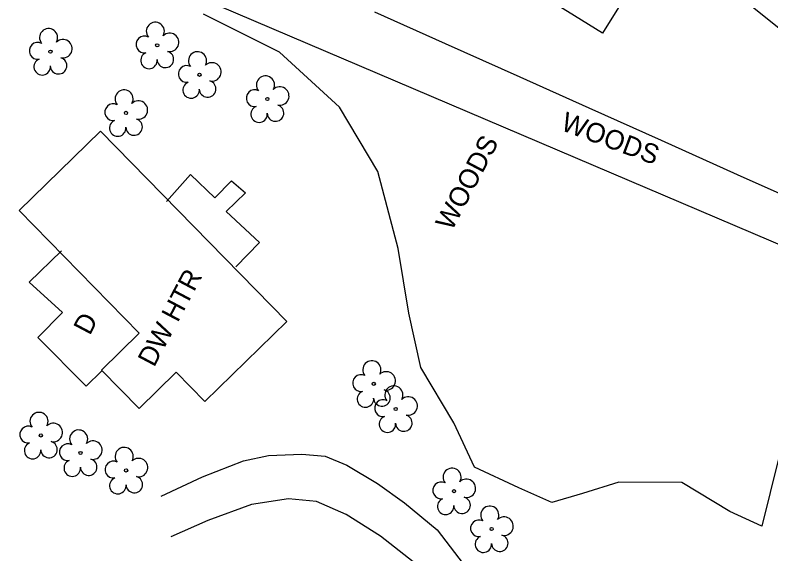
# Model space of a CAD drawing. Extents: x 1149843 to 1151668, y 621784 to 624721.
# Drawn here: x 1150484.2 to 1150639.4, y 623160.4 to 623271.1 of the extents above; entities that cross this region are included whole.
import ezdxf

# ---------------------------------------------------------------- set-up
doc = ezdxf.new("R2010")
doc.units = 0
for name, color, linetype in [('Exist Building', 7, 'Continuous'), ('Exist Building Text', 7, 'Continuous'), ('Exist Other Culture Area Outline', 7, 'Continuous'), ('Exist Other Culture Area Outline Text', 7, 'Continuous'), ('Exist Property Line', 7, 'Continuous'), ('Exist Roads Soil', 7, 'Continuous'), ('Exist Utilities Power UG Cable SUE', 7, 'Continuous'), ('Exist Vegetation Tree CELL', 7, 'Continuous'), ('Exist Vegetation Woods Line', 7, 'Continuous'), ('Exist Vegetation Woods Line Text', 7, 'Continuous')]:
    doc.layers.add(name, color=color, linetype=linetype)

msp = doc.modelspace()

# ---------------------------------------------------------------- linework, layer by layer
at = {"layer": 'Exist Building'}
for points in [[(1150604.77, 623267.36), (1150590.97, 623275.97), (1150597.72, 623286.8), (1150611.53, 623278.19)], [(1150501.76, 623247.25), (1150540, 623208.17), (1150523.17, 623191.7), (1150517.25, 623197.75), (1150509.65, 623190.31), (1150501.95, 623198.18), (1150509.69, 623205.74), (1150485.06, 623230.91)]]:
    msp.add_lwpolyline(points, close=True, dxfattribs=at)
at = {"layer": 'Exist Other Culture Area Outline'}
for points in [[(1150515.27, 623232.81), (1150520.21, 623238.32), (1150525.25, 623233.57), (1150528.63, 623237.01), (1150531.53, 623234.57), (1150527.52, 623230.72), (1150534.38, 623224.4), (1150529.54, 623219.36)], [(1150493.74, 623222.68), (1150487.07, 623216.23), (1150493.96, 623209.96), (1150488.91, 623204.88), (1150498.8, 623194.86), (1150502.02, 623197.99)]]:
    msp.add_lwpolyline(points, dxfattribs=at)
at = {"layer": 'Exist Property Line'}
msp.add_line((1150220.73, 623403.16), (1150704.95, 623196.74), dxfattribs=at)
at = {"layer": 'Exist Roads Soil'}
for points in [[(1150514.2, 623172.26), (1150522.71, 623176.23), (1150531.12, 623179.54), (1150536.24, 623180.65), (1150543.08, 623180.92), (1150547.86, 623180.49), (1150552.32, 623178.64), (1150558.64, 623174.89), (1150564.18, 623170.9), (1150570.87, 623165.34), (1150577.1, 623157.23), (1150585.07, 623144.02), (1150593.33, 623126.07), (1150599.51, 623111.6), (1150603.78, 623098.72), (1150608, 623086.29), (1150611.91, 623071.88), (1150616.83, 623060.13), (1150620.21, 623054.9)], [(1150606.55, 623064.28), (1150602.64, 623077.14), (1150596.78, 623095.46), (1150592.23, 623109.09), (1150586.2, 623126.59), (1150577.23, 623145.28), (1150572.12, 623152.47), (1150566.89, 623158.02), (1150559.2, 623164.09), (1150552.15, 623168.48), (1150546.12, 623171.19), (1150540.33, 623171.73), (1150532.77, 623170.53), (1150523.75, 623167.29), (1150516.15, 623163.9)]]:
    msp.add_lwpolyline(points, dxfattribs=at)
at = {"layer": 'Exist Utilities Power UG Cable SUE'}
msp.add_lwpolyline([(1150633.5, 623274.51), (1150655.87, 623256.56), (1150671.72, 623238.23), (1150681.72, 623223.65), (1150687.35, 623201.98)], dxfattribs=at)
at = {"layer": 'Exist Vegetation Tree CELL'}
for p, q in [((1150513.39, 623264.87), (1150513.39, 623264.87)), ((1150491.47, 623263.57), (1150491.47, 623263.57)), ((1150522.06, 623258.81), (1150522.06, 623258.81)), ((1150536.01, 623253.85), (1150536.01, 623253.85)), ((1150506.98, 623250.98), (1150506.98, 623250.98)), ((1150557.84, 623195.35), (1150557.84, 623195.35)), ((1150562.35, 623190.19), (1150562.35, 623190.19)), ((1150489.5, 623184.75), (1150489.5, 623184.75)), ((1150497.64, 623181.14), (1150497.64, 623181.14)), ((1150507, 623177.56), (1150507, 623177.56)), ((1150574.3, 623173.3), (1150574.3, 623173.3)), ((1150582.04, 623165.52), (1150582.04, 623165.52))]:
    msp.add_line(p, q, dxfattribs=at)
for centre in [(1150513.39, 623264.87), (1150491.47, 623263.57), (1150522.06, 623258.81), (1150536.01, 623253.85), (1150506.98, 623250.98), (1150557.84, 623195.35), (1150562.35, 623190.19), (1150489.5, 623184.75), (1150497.64, 623181.14), (1150507, 623177.56), (1150574.3, 623173.3), (1150582.04, 623165.52)]:
    msp.add_circle(centre, 0.326, dxfattribs=at)
for centre, radius, start, end in [((1150513, 623267.74), 1.86, 330.1651, 219.7134), ((1150491.09, 623266.44), 1.86, 330.1651, 219.7134), ((1150515.94, 623265.46), 1.9, 257.1011, 134.1999), ((1150494.02, 623264.16), 1.9, 257.1011, 134.1999), ((1150510.78, 623265.02), 1.73, 62.6636, 279.3457), ((1150488.86, 623263.72), 1.73, 62.6636, 279.3457), ((1150511.69, 623261.75), 1.69, 111.5671, 6.231), ((1150515.06, 623261.97), 1.7, 181.2822, 74.56), ((1150521.67, 623261.69), 1.86, 330.1651, 219.7134), ((1150489.77, 623260.45), 1.69, 111.5671, 6.231), ((1150493.14, 623260.67), 1.7, 181.2822, 74.56), ((1150524.61, 623259.4), 1.9, 257.1011, 134.1999), ((1150519.45, 623258.97), 1.73, 62.6636, 279.3457), ((1150535.62, 623256.72), 1.86, 330.1651, 219.7134), ((1150520.35, 623255.69), 1.69, 111.5671, 6.231), ((1150523.73, 623255.91), 1.7, 181.2822, 74.56), ((1150506.59, 623253.85), 1.86, 330.1651, 219.7134), ((1150533.4, 623254), 1.73, 62.6636, 279.3457), ((1150538.55, 623254.44), 1.9, 257.1011, 134.1999), ((1150509.53, 623251.57), 1.9, 257.1011, 134.1999), ((1150504.37, 623251.13), 1.73, 62.6636, 279.3457), ((1150534.3, 623250.73), 1.69, 111.5671, 6.231), ((1150537.68, 623250.95), 1.7, 181.2822, 74.56), ((1150505.27, 623247.86), 1.69, 111.5671, 6.231), ((1150508.65, 623248.08), 1.7, 181.2822, 74.56), ((1150557.46, 623198.23), 1.86, 330.1651, 219.7134), ((1150560.39, 623195.94), 1.9, 257.1011, 134.1999), ((1150555.24, 623195.51), 1.73, 62.6636, 279.3457), ((1150561.97, 623193.07), 1.86, 330.1651, 219.7134), ((1150556.14, 623192.23), 1.69, 111.5671, 6.231), ((1150559.52, 623192.45), 1.7, 181.2822, 74.56), ((1150559.74, 623190.35), 1.73, 62.6636, 279.3457), ((1150564.9, 623190.78), 1.9, 257.1011, 134.1999), ((1150489.12, 623187.63), 1.86, 330.1651, 219.7134), ((1150560.65, 623187.07), 1.69, 111.5671, 6.231), ((1150564.02, 623187.29), 1.7, 181.2822, 74.56), ((1150486.9, 623184.91), 1.73, 62.6636, 279.3457), ((1150492.05, 623185.34), 1.9, 257.1011, 134.1999), ((1150497.26, 623184.01), 1.86, 330.1651, 219.7134), ((1150500.19, 623181.73), 1.9, 257.1011, 134.1999), ((1150487.8, 623181.63), 1.69, 111.5671, 6.231), ((1150491.17, 623181.85), 1.7, 181.2822, 74.56), ((1150495.04, 623181.29), 1.73, 62.6636, 279.3457), ((1150506.62, 623180.44), 1.86, 330.1651, 219.7134), ((1150495.94, 623178.02), 1.69, 111.5671, 6.231), ((1150499.32, 623178.24), 1.7, 181.2822, 74.56), ((1150504.4, 623177.72), 1.73, 62.6636, 279.3457), ((1150509.55, 623178.15), 1.9, 257.1011, 134.1999), ((1150573.92, 623176.17), 1.86, 330.1651, 219.7134), ((1150505.3, 623174.44), 1.69, 111.5671, 6.231), ((1150508.68, 623174.67), 1.7, 181.2822, 74.56), ((1150576.85, 623173.89), 1.9, 257.1011, 134.1999), ((1150571.7, 623173.45), 1.73, 62.6636, 279.3457), ((1150572.6, 623170.18), 1.69, 111.5671, 6.231), ((1150575.97, 623170.4), 1.7, 181.2822, 74.56), ((1150581.66, 623168.39), 1.86, 330.1651, 219.7134), ((1150584.59, 623166.11), 1.9, 257.1011, 134.1999), ((1150579.44, 623165.67), 1.73, 62.6636, 279.3457), ((1150580.34, 623162.4), 1.69, 111.5671, 6.231), ((1150583.71, 623162.62), 1.7, 181.2822, 74.56)]:
    msp.add_arc(centre, radius, start, end, dxfattribs=at)
at = {"layer": 'Exist Vegetation Woods Line'}
for points in [[(1150644.39, 623194.07), (1150637.54, 623166.13), (1150630.92, 623169.12), (1150621.1, 623175.08), (1150608.18, 623175.12), (1150600.66, 623172.79), (1150594.42, 623170.97), (1150587.61, 623173.97), (1150578.51, 623178.25), (1150574.31, 623187.33), (1150567.53, 623198.68), (1150565.04, 623209.88), (1150562.87, 623223.16), (1150558.68, 623238.96), (1150550.83, 623252.19), (1150538.48, 623263.47), (1150522.9, 623271.24)], [(1150558, 623271.74), (1150572.48, 623265.25), (1150587.82, 623258.37), (1150602.02, 623252), (1150616.84, 623245.36), (1150632.46, 623238.36), (1150647.96, 623231.41)]]:
    msp.add_lwpolyline(points, dxfattribs=at)

# ---------------------------------------------------------------- texts
at = {"layer": 'Exist Building Text'}
msp.add_text('DW HTR', height=4, rotation=62.15, dxfattribs=at).set_placement((1150512.74, 623198.6))
at = {"layer": 'Exist Other Culture Area Outline Text'}
msp.add_text('D', height=4, rotation=62.15, dxfattribs=at).set_placement((1150499.54, 623205.13))
at = {"layer": 'Exist Vegetation Woods Line Text'}
for rotation, p in [(339.5233, (1150596.02, 623247.53)), (62.1899, (1150573.87, 623226.57))]:
    msp.add_text('WOODS', height=4, rotation=rotation, dxfattribs=at).set_placement(p)

doc.saveas('drawing.dxf')
